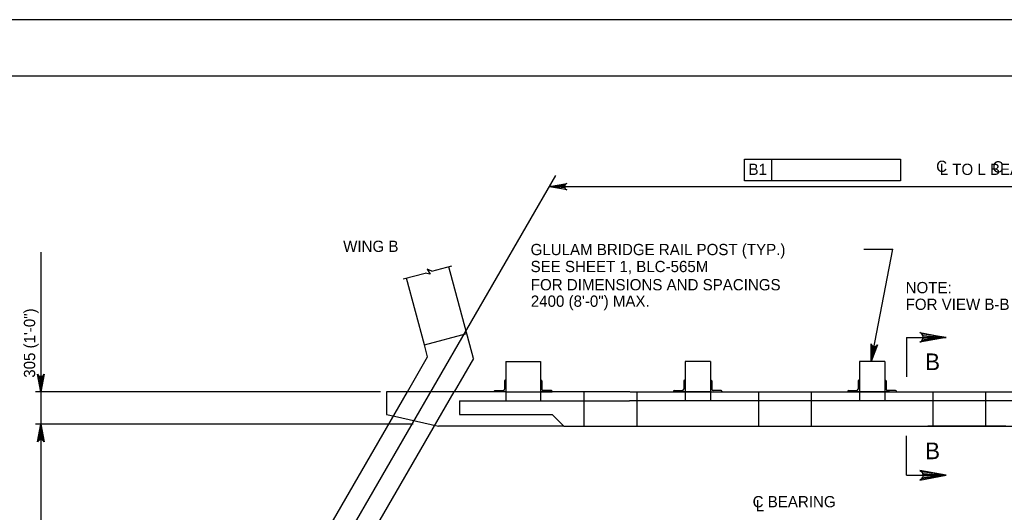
# Model space of a CAD drawing. Extents: x 638268 to 640277, y 295465 to 298435.
# Drawn here: x 638488.1 to 638750, y 298304.3 to 298435.5 of the extents above; entities that cross this region are included whole.
import ezdxf

# ---------------------------------------------------------------- set-up
doc = ezdxf.new("R2010")
doc.units = 0
for name, color, linetype in [('2', 7, 'Continuous'), ('3', 7, 'Continuous'), ('4', 7, 'Continuous'), ('PLT-BNDY', 7, 'Continuous')]:
    doc.layers.add(name, color=color, linetype=linetype)

msp = doc.modelspace()

# ---------------------------------------------------------------- linework, layer by layer
at = {"layer": '2'}
for p, q in [((638475.46, 298420.46), (639261.46, 298420.46)), ((638608.8, 298345.27), (638602.26, 298369.68)), ((638595.78, 298348.87), (638591.01, 298366.66)), ((638595.78, 298348.87), (638607.02, 298351.89)), ((638596.62, 298345.72), (638595.78, 298348.87)), ((638723.98, 298350.87), (638723.98, 298340.39)), ((638723.98, 298350.87), (638734.47, 298350.87)), ((638591.22, 298336.37), (638596.62, 298345.72)), ((638608.8, 298345.27), (638603.66, 298336.37)), ((638617.4, 298344.46), (638626.64, 298344.46)), ((638617.4, 298344.46), (638617.4, 298333.98)), ((638626.64, 298344.46), (638626.64, 298333.98)), ((638671.79, 298344.46), (638665.07, 298344.46)), ((638665.07, 298344.46), (638665.07, 298333.98)), ((638671.79, 298344.46), (638671.79, 298333.98)), ((638718.16, 298344.46), (638711.43, 298344.46)), ((638718.16, 298344.46), (638711.43, 298344.46)), ((638711.43, 298344.46), (638711.43, 298333.98)), ((638718.16, 298344.46), (638718.16, 298333.98)), ((638617.04, 298339.28), (638617.04, 298337.1)), ((638617.22, 298339.46), (638617.4, 298339.46)), ((638617.4, 298339.46), (638617.4, 298336.37)), ((638626.82, 298339.46), (638626.64, 298339.46)), ((638626.64, 298339.46), (638626.64, 298336.37)), ((638627, 298339.28), (638627, 298337.1)), ((638664.7, 298339.28), (638664.7, 298337.1)), ((638664.89, 298339.46), (638665.07, 298339.46)), ((638665.07, 298339.46), (638665.07, 298336.37)), ((638671.98, 298339.46), (638671.79, 298339.46)), ((638671.79, 298339.46), (638671.79, 298336.37)), ((638672.16, 298339.28), (638672.16, 298337.1)), ((638711.07, 298339.28), (638711.07, 298337.1)), ((638711.25, 298339.46), (638711.43, 298339.46)), ((638711.43, 298339.46), (638711.43, 298336.37)), ((638718.34, 298339.46), (638718.16, 298339.46)), ((638718.16, 298339.46), (638718.16, 298336.37)), ((638718.52, 298339.28), (638718.52, 298337.1)), ((638527.04, 298225.2), (638591.22, 298336.37)), ((638539.47, 298225.2), (638603.66, 298336.37)), ((638585.66, 298336.37), (638585.66, 298330.34)), ((638617.4, 298336.37), (638585.66, 298336.37)), ((638614.31, 298336.55), (638614.31, 298336.37)), ((638617.4, 298336.37), (638614.31, 298336.37)), ((638614.49, 298336.73), (638616.68, 298336.73)), ((638617.4, 298336.37), (638626.64, 298336.37)), ((638626.64, 298336.37), (638629.73, 298336.37)), ((638650.35, 298336.37), (638626.64, 298336.37)), ((638629.55, 298336.73), (638627.37, 298336.73)), ((638629.73, 298336.55), (638629.73, 298336.37)), ((638638.19, 298336.37), (638638.19, 298327.25)), ((638650.43, 298336.37), (638797.52, 298336.37)), ((638652.26, 298336.37), (638652.26, 298327.25)), ((638661.98, 298336.55), (638661.98, 298336.37)), ((638665.07, 298336.37), (638661.98, 298336.37)), ((638662.16, 298336.73), (638664.34, 298336.73)), ((638671.79, 298336.37), (638665.07, 298336.37)), ((638671.79, 298336.37), (638674.88, 298336.37)), ((638674.7, 298336.73), (638672.52, 298336.73)), ((638674.88, 298336.55), (638674.88, 298336.37)), ((638684.6, 298336.37), (638684.6, 298327.25)), ((638698.62, 298336.37), (638698.62, 298327.25)), ((638708.34, 298336.55), (638708.34, 298336.37)), ((638711.43, 298336.37), (638708.34, 298336.37)), ((638708.52, 298336.73), (638710.7, 298336.73)), ((638719.41, 298336.37), (638710.18, 298336.37)), ((638718.16, 298336.37), (638711.43, 298336.37)), ((638718.16, 298336.37), (638721.25, 298336.37)), ((638721.07, 298336.73), (638718.88, 298336.73)), ((638721.25, 298336.55), (638721.25, 298336.37)), ((638730.96, 298336.37), (638730.96, 298327.25)), ((638744.99, 298336.37), (638744.99, 298327.25)), ((638605.08, 298333.98), (638650.25, 298333.98)), ((638605.08, 298333.98), (638605.08, 298330.34)), ((638778.1, 298333.98), (638650.25, 298333.98)), ((638585.66, 298330.34), (638587.83, 298329.86)), ((638605.08, 298330.34), (638629.72, 298330.34)), ((638632.81, 298327.25), (638629.72, 298330.34)), ((638587.83, 298329.86), (638599.51, 298327.25)), ((638632.81, 298327.25), (638599.51, 298327.25)), ((638632.81, 298327.25), (638648.97, 298327.25)), ((638632.81, 298327.25), (638783.67, 298327.25)), ((638750.37, 298327.25), (638729.59, 298327.25)), ((638723.98, 298314.14), (638723.98, 298324.63)), ((638723.98, 298314.14), (638734.47, 298314.14))]:
    msp.add_line(p, q, dxfattribs=at)
for points in [[(638734.47, 298350.87), (638727.48, 298349.56), (638728.01, 298349.93), (638728.29, 298350.4), (638728.37, 298350.87), (638728.29, 298351.34), (638728.01, 298351.81), (638727.48, 298352.18), (638734.47, 298350.87), (638728.01, 298351.81), (638728.29, 298351.34), (638734.47, 298350.87), (638728.37, 298350.87), (638728.29, 298350.4), (638734.47, 298350.87), (638728.01, 298349.93)], [(638734.47, 298314.14), (638727.48, 298315.45), (638728.01, 298315.08), (638728.29, 298314.61), (638728.37, 298314.14), (638728.29, 298313.67), (638728.01, 298313.2), (638727.48, 298312.83), (638734.47, 298314.14), (638728.01, 298313.2), (638728.29, 298313.67), (638734.47, 298314.14), (638728.37, 298314.14), (638728.29, 298314.61), (638734.47, 298314.14), (638728.01, 298315.08)]]:
    msp.add_lwpolyline(points, dxfattribs=at)
for centre, radius, start, end in [((638617.22, 298339.28), 0.182, 90, 179.9984), ((638626.82, 298339.28), 0.182, 0.0016, 90), ((638664.89, 298339.28), 0.182, 90, 179.9984), ((638671.98, 298339.28), 0.182, 0.0016, 90), ((638711.25, 298339.28), 0.182, 90, 179.9984), ((638718.34, 298339.28), 0.182, 0.0016, 90), ((638614.49, 298336.55), 0.182, 90, 179.9984), ((638616.68, 298337.1), 0.364, 270, 359.9984), ((638627.37, 298337.1), 0.364, 180.0016, 270), ((638629.55, 298336.55), 0.182, 0.0016, 90), ((638662.16, 298336.55), 0.182, 90, 179.9984), ((638664.34, 298337.1), 0.364, 270, 359.9984), ((638672.52, 298337.1), 0.364, 180.0016, 270), ((638674.7, 298336.55), 0.182, 0.0016, 90), ((638708.52, 298336.55), 0.182, 90, 179.9984), ((638710.7, 298337.1), 0.364, 270, 359.9984), ((638718.88, 298337.1), 0.364, 180.0016, 270), ((638721.07, 298336.55), 0.182, 0.0016, 90)]:
    msp.add_arc(centre, radius, start, end, dxfattribs=at)
at = {"layer": '3'}
for p, q in [((638498.88, 298165.66), (638630.71, 298394)), ((638597.71, 298368.46), (638603.05, 298369.89)), ((638590.14, 298366.43), (638595.98, 298367.99)), ((638597.32, 298367.7), (638595.98, 298367.99)), ((638596.46, 298369), (638597.32, 298367.7)), ((638597.71, 298368.46), (638596.46, 298369))]:
    msp.add_line(p, q, dxfattribs=at)
at = {"layer": '4'}
for p, q in [((638680.88, 298398.35), (638688.11, 298398.35)), ((638680.88, 298392.59), (638680.88, 298398.35)), ((638688.11, 298392.59), (638688.11, 298398.35)), ((638688.11, 298398.35), (638722.4, 298398.35)), ((638722.4, 298398.35), (638722.4, 298392.59)), ((638628.98, 298391), (638820.39, 298391)), ((638722.4, 298392.59), (638680.88, 298392.59)), ((638493.78, 298373.54), (638493.78, 298192.11)), ((638712.63, 298374.31), (638720.36, 298374.31)), ((638714.52, 298344.45), (638720.36, 298374.31)), ((638584.09, 298336.37), (638492.34, 298336.37)), ((638592.81, 298327.72), (638492.34, 298327.72))]:
    msp.add_line(p, q, dxfattribs=at)
for points in [[(638628.98, 298391), (638633.64, 298391.87), (638633.28, 298391.62), (638633.09, 298391.31), (638633.04, 298391), (638633.09, 298390.68), (638633.28, 298390.37), (638633.64, 298390.12), (638628.98, 298391), (638633.28, 298390.37), (638633.09, 298390.68), (638628.98, 298391), (638633.04, 298391), (638633.09, 298391.31), (638628.98, 298391), (638633.28, 298391.62)], [(638714.52, 298344.45), (638714.56, 298349.19), (638714.73, 298348.79), (638715, 298348.55), (638715.3, 298348.44), (638715.62, 298348.43), (638715.96, 298348.55), (638716.27, 298348.86), (638714.52, 298344.45), (638715.96, 298348.55), (638715.62, 298348.43), (638714.52, 298344.45), (638715.3, 298348.44), (638715, 298348.55), (638714.52, 298344.45), (638714.73, 298348.79)], [(638493.78, 298336.37), (638492.9, 298341.03), (638493.15, 298340.67), (638493.46, 298340.49), (638493.78, 298340.44), (638494.09, 298340.49), (638494.4, 298340.67), (638494.65, 298341.03), (638493.78, 298336.37), (638494.4, 298340.67), (638494.09, 298340.49), (638493.78, 298336.37), (638493.78, 298340.44), (638493.46, 298340.49), (638493.78, 298336.37), (638493.15, 298340.67)], [(638493.78, 298327.72), (638494.65, 298323.06), (638494.4, 298323.42), (638494.09, 298323.6), (638493.78, 298323.66), (638493.46, 298323.6), (638493.15, 298323.42), (638492.9, 298323.06), (638493.78, 298327.72), (638493.15, 298323.42), (638493.46, 298323.6), (638493.78, 298327.72), (638493.78, 298323.66), (638494.09, 298323.6), (638493.78, 298327.72), (638494.4, 298323.42)]]:
    msp.add_lwpolyline(points, dxfattribs=at)
for points in [[(638493.3, 298339.26), (638494.26, 298339.26), (638493.78, 298336.37)], [(638493.3, 298324.84), (638494.26, 298324.84), (638493.78, 298327.72)]]:
    msp.add_lwpolyline(points, close=True, dxfattribs=at)
at = {"layer": 'PLT-BNDY'}
msp.add_lwpolyline([(638435.46, 298435.46), (639276.46, 298435.46), (639276.46, 297841.46), (638435.46, 297841.46)], close=True, dxfattribs=at)

# ---------------------------------------------------------------- texts
at = {"layer": '4'}
for s, height, p in [('B1', 3, (638681.94, 298394.11)), ('C', 3, (638731.85, 298394.91)), ('L TO L BEARINGS', 3, (638732.77, 298394.11)), ('C', 3, (638746.81, 298394.77)), ('WING B', 3, (638574.15, 298373.61)), ('GLULAM BRIDGE RAIL POST (TYP.)', 3, (638623.99, 298372.76)), ('SEE SHEET 1, BLC-565M', 3, (638623.99, 298368.24)), ('FOR DIMENSIONS AND SPACINGS', 3, (638624.05, 298363.39)), ('NOTE:', 3, (638723.72, 298362.62)), ('2400 (8\'-0") MAX.', 3, (638624.05, 298359.01)), ('FOR VIEW B-B SEE SHEET 4.', 3, (638723.72, 298358.18)), ('B', 4.43, (638728.92, 298318.44)), ('C BEARING', 3, (638683.04, 298305.62)), ('L', 3, (638683.86, 298304.56))]:
    msp.add_text(s, height=height, dxfattribs=at).set_placement(p)
for s, height, rotation, p in [('305 (1\'-0")', 3, 90, (638492.25, 298340.11)), ('B', 4.43, 360, (638728.92, 298342.15))]:
    msp.add_text(s, height=height, rotation=rotation, dxfattribs=at).set_placement(p)

doc.saveas('drawing.dxf')
